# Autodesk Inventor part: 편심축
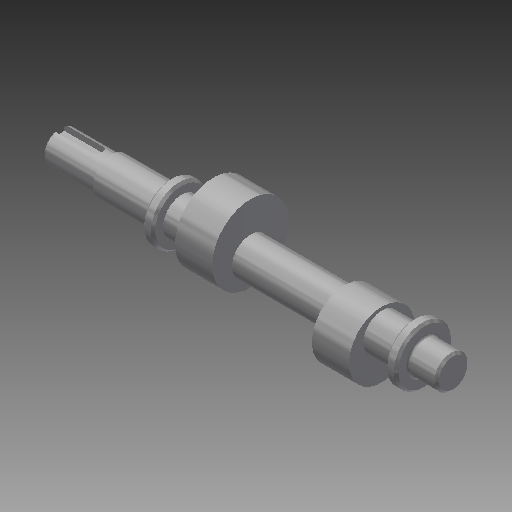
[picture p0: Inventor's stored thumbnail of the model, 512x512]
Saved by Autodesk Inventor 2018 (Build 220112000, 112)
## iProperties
Created: 2021-06
Part Number: 편심축
Material: 강철, 연강
Document SubType Name: Modeling
Designer: mdu-edu
Density: 7.86 g/cm^3
Appearance: 강철
Author: mdu-edu
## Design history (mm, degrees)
sketch "스케치1"
  geometry: L1 (0, 0)-(180, 0); L2 (180, 0)-(180, -7.5); L3 (180, -7.5)-(167, -7.5); L4 (167, -7.5)-(167, -13); L5 (167, -13)-(162, -13); L6 (162, -13)-(162, -8.5); L7 (162, -8.5)-(56, -8.5); L8 (56, -8.5)-(56, -13); L9 (56, -13)-(51, -13); L10 (51, -13)-(51, -8.5); L11 (51, -8.5)-(24, -8.5); L12 (24, -8.5)-(24, -7.5); L13 (24, -7.5)-(0, -7.5); L14 (0, -7.5)-(0, 0)
  constraints: 28 end point, 6 parallel, 3 horizontal, 3 vertical, 1 collinear, 1 perpendicular
  dimensions: "d0" = 15 diameter of L13 L1; "d2" = 26 diameter of L9 L1; "d3" = 26 diameter of L5 L1; "d4" = 15 diameter of L3 L1; "d5" = 17 diameter of L7 L1; "d6" = 17 diameter of L11 L1; "d7" = 24 distance between parallel lines of L12 L14; "d8" = 51 distance between parallel lines of L14 L10; "d10" = 5 distance of L8.end L9.end; "d11" = 5 distance of L4.end L5.end; "d12" = 13 distance between parallel lines of L4 L2; "d13" = 180 distance between parallel lines of L14 L2
revolve "회전1" sketch "스케치1" stored, may be unused: angle "d14" = 90 deg
node "작업 평면1"
sketch "스케치2"
  geometry: C1 r 17.5 at (0, 5); 1 further point
  constraints: 1 centre point, 1 vertical alignment
  dimensions: "d16" = 35 diameter of C1; "d17" = 5 distance of C1.centre point (0, 0)
extrude "돌출1" join sketch "스케치2" distance "d18" = 17; taper "d19" = 0 deg
node "작업 평면2"
sketch "스케치3"
  geometry: C1 r 15 at (0, -5); 1 further point
  constraints: 1 centre point, 1 vertical alignment
  dimensions: "d21" = 30 diameter of C1; "d22" = 5 distance of point (0, 0) C1.centre
extrude "돌출2" join sketch "스케치3" distance "d23" = 17; taper "d24" = 0 deg
chamfer "모따기1" distance "d29" = 1; stored, may be unused: second distance "d30" = 2, angle "d31" = 45 deg
node "작업 평면3"
sketch "스케치4"
  geometry: L1 (-5.5, 2.5)-(12, 2.5); L2 (12, 2.5)-(12, -2.5); L3 (12, -2.5)-(-5.5, -2.5); L4 (12, 6.5)-(12, -6.5) reference; A1 r 2.5 centre (-5.5, 0) between (-5.5, 2.5) and (-5.5, -2.5); 1 further point
  constraints: 6 end point, 2 point on circle, 2 tangent, 1 centre point, 1 collinear, 1 horizontal, 1 horizontal alignment, 1 midpoint, 1 parallel, 1 perpendicular
  dimensions: "d25" = 5 diameter of A1; "d32" = 20 dimension on A1 L4
extrude "돌출3" cut sketch "스케치4" distance "d27" = 3; taper "d28" = 0 deg
fillet "모깎기1" dims "d33" = 0.6
fillet "모깎기2" dims "d34" = 1
node "솔리드1"
other parameters: "d15" = -70.5, "d20" = -32.5
